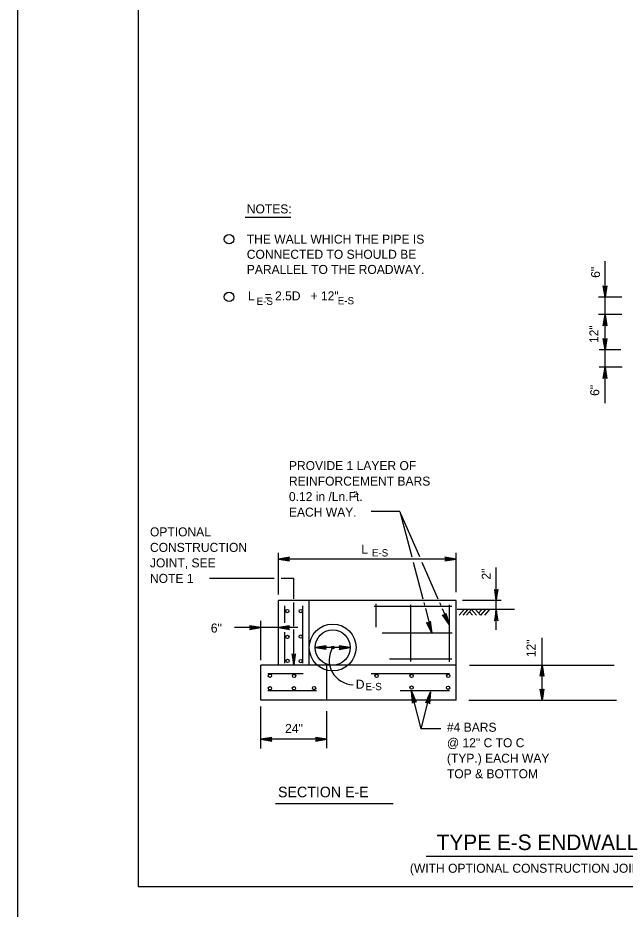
# Model space of a CAD drawing. Extents: x 638877 to 639960, y 297341 to 299123.
# Drawn here: x 638877.2 to 639079.3, y 297942.8 to 298239.6 of the extents above; entities that cross this region are included whole.
import ezdxf

# ---------------------------------------------------------------- set-up
doc = ezdxf.new("R2010")
doc.units = 0
for name, color, linetype in [('1', 7, 'Continuous'), ('2', 7, 'Continuous'), ('3', 7, 'Continuous'), ('PLT-BNDY', 7, 'Continuous')]:
    doc.layers.add(name, color=color, linetype=linetype)

msp = doc.modelspace()

# ---------------------------------------------------------------- linework, layer by layer
at = {"layer": '1'}
for p, q in [((638917.19, 298514.28), (638917.19, 297950.28)), ((639025.67, 298042.52), (639024.05, 298040.69)), ((639026.82, 298042.48), (639025.24, 298040.69)), ((639028.14, 298042.52), (639026.52, 298040.69)), ((639028.14, 298042.52), (639029.79, 298040.69)), ((639029.46, 298042.52), (639031.12, 298040.69)), ((639031.43, 298042.48), (639030.47, 298041.4)), ((639032.66, 298042.44), (639031.12, 298040.69)), ((639034.03, 298042.48), (639032.41, 298040.64)), ((639027.54, 298041.71), (639028.47, 298040.69)), ((639021.72, 298034.74), (638998.36, 298034.74)), ((638917.19, 297950.28), (639703.19, 297950.28))]:
    msp.add_line(p, q, dxfattribs=at)
for centre, radius in [((638947.46, 298165.86), 1.58), ((638947.46, 298146.66), 1.58), ((638966.85, 298042.05), 0.554), ((638971.31, 298042.05), 0.554), ((638981.95, 298029.91), 7.8), ((638966.88, 298033.46), 0.554), ((638971.31, 298033.57), 0.554), ((638981.95, 298029.91), 0.452), ((638966.93, 298025.47), 0.554), ((638971.31, 298025.37), 0.554), ((638961.06, 298020.51), 0.554), ((638969.08, 298020.44), 0.554), ((638996.57, 298020.47), 0.554), ((639008.21, 298020.46), 0.554), ((639020.38, 298020.44), 0.554), ((638961.04, 298016.35), 0.554), ((638969.04, 298016.33), 0.554), ((638975.75, 298016.38), 0.554), ((639008.19, 298016.59), 0.554), ((639020.35, 298016.49), 0.554)]:
    msp.add_circle(centre, radius, dxfattribs=at)
msp.add_arc((638988.96, 298025.7), 8.18, 149.0183, 268.6465, dxfattribs=at)
at = {"layer": '2'}
for p, q in [((638952.88, 298173.26), (638967.97, 298173.26)), ((639072.57, 298140.77), (639072.57, 298158.6)), ((639078.16, 298146.62), (639070.44, 298146.62)), ((639078.16, 298140.77), (639070.44, 298140.77)), ((639072.57, 298129.07), (639072.57, 298140.77)), ((639077.87, 298129.07), (639070.58, 298129.07)), ((639072.57, 298111.24), (639072.57, 298129.07)), ((639078.3, 298123.22), (639070.58, 298123.22)), ((639004.32, 298075.22), (638994.72, 298075.22)), ((639004.32, 298075.22), (639008.28, 298060.14)), ((639004.59, 298074.35), (639010.8, 298060.2)), ((638963.88, 298047.53), (638963.88, 298061.49)), ((639023.03, 298048.29), (639023.03, 298061.49)), ((639023.03, 298059.37), (638963.88, 298059.37)), ((639008.77, 298058.28), (639011.95, 298046.15)), ((639011.63, 298058.31), (639016.95, 298046.16)), ((639036.39, 298035.76), (639036.39, 298056.6)), ((638962.46, 298052.87), (638940.93, 298052.87)), ((638969.01, 298052.87), (638964.78, 298052.87)), ((638969.01, 298046.16), (638969.01, 298052.87)), ((638963.88, 298024.06), (638963.88, 298045.51)), ((639023.03, 298045.51), (638963.88, 298045.51)), ((638974.15, 298024.06), (638974.15, 298045.51)), ((639012.27, 298044.93), (639012.5, 298044.06)), ((639023.03, 298012.36), (639023.03, 298045.51)), ((639038.06, 298045.51), (639025.09, 298045.51)), ((638966.08, 298038.08), (638966.08, 298043.77)), ((638969.01, 298037.06), (638969.01, 298044.9)), ((638971.98, 298024.73), (638971.98, 298043.77)), ((639021.56, 298043.56), (638995.71, 298043.56)), ((638996.46, 298036.68), (638996.46, 298044.4)), ((639007.93, 298025.27), (639007.93, 298044.17)), ((639012.8, 298042.95), (639014.95, 298034.74)), ((639017.51, 298044.91), (639017.88, 298044.05)), ((639018.41, 298042.85), (639020.74, 298037.54)), ((639020.81, 298025.19), (639020.81, 298044.17)), ((639042.49, 298042.56), (639023.35, 298042.56)), ((638963.88, 298036.52), (638949.26, 298036.52)), ((638958.03, 298025.66), (638958.03, 298038.79)), ((638970.4, 298036.52), (638963.88, 298036.52)), ((638966.08, 298024.73), (638966.08, 298035.01)), ((638969.01, 298024.06), (638969.01, 298035.89)), ((639051.63, 298024.06), (639051.63, 298033.12)), ((638987.8, 298029.91), (638976.1, 298029.91)), ((638981.95, 298029.91), (638981.95, 298029.91)), ((639021.56, 298026.05), (639000.89, 298026.05)), ((638963.88, 298024.06), (638958.03, 298024.06)), ((638958.03, 298012.36), (638958.03, 298024.06)), ((638972.16, 298021.19), (638960.39, 298021.19)), ((638974.15, 298024.06), (638963.88, 298024.06)), ((639023.03, 298024.06), (638974.15, 298024.06)), ((638980, 298012.36), (638980, 298024.06)), ((639020.83, 298021.19), (638994.74, 298021.19)), ((639027.47, 298024.06), (639075.6, 298024.06)), ((639051.63, 298012.36), (639051.63, 298024.06)), ((638976.6, 298015.52), (638960.39, 298015.52)), ((639020.83, 298015.52), (639004.44, 298015.52)), ((639011.34, 298002.78), (639008.12, 298015.35)), ((639023.03, 298012.36), (638958.03, 298012.36)), ((639011.34, 298002.78), (639014.52, 298015.14)), ((639027.2, 298012.36), (639076.42, 298012.36)), ((638958.03, 297996.32), (638958.03, 298010.25)), ((638980, 297996.42), (638980, 298008.74)), ((639017.92, 298002.78), (639011.34, 298002.78)), ((638980, 297999.37), (638958.03, 297999.37))]:
    msp.add_line(p, q, dxfattribs=at)
for points in [[(639073.01, 298150.17), (639072.75, 298150.03), (639072.57, 298146.62), (639073.01, 298150.17), (639073.17, 298150.35), (639072.57, 298146.62), (639072.4, 298150.03), (639072.15, 298150.15), (639072.57, 298146.62), (639071.97, 298150.35), (639072.15, 298150.15)], [(639072.12, 298137.23), (639072.38, 298137.37), (639072.57, 298140.77), (639072.12, 298137.23), (639071.97, 298137.05), (639072.57, 298140.77), (639072.74, 298137.37), (639072.99, 298137.24), (639072.57, 298140.77), (639073.16, 298137.05), (639072.99, 298137.24)], [(639073.01, 298132.62), (639072.75, 298132.48), (639072.57, 298129.07), (639073.01, 298132.62), (639073.17, 298132.8), (639072.57, 298129.07), (639072.4, 298132.48), (639072.15, 298132.6), (639072.57, 298129.07), (639071.97, 298132.8), (639072.15, 298132.6)], [(639072.12, 298119.68), (639072.38, 298119.82), (639072.57, 298123.22), (639072.12, 298119.68), (639071.97, 298119.5), (639072.57, 298123.22), (639072.74, 298119.82), (639072.99, 298119.69), (639072.57, 298123.22), (639073.16, 298119.5), (639072.99, 298119.69)], [(638967.42, 298059.81), (638967.29, 298059.56), (638963.88, 298059.37), (638967.42, 298059.81), (638967.6, 298059.97), (638963.88, 298059.37), (638967.28, 298059.2), (638967.41, 298058.95), (638963.88, 298059.37), (638967.6, 298058.78), (638967.41, 298058.95)], [(639019.49, 298058.92), (639019.62, 298059.18), (639023.03, 298059.37), (639019.49, 298058.92), (639019.3, 298058.77), (639023.03, 298059.37), (639019.62, 298059.54), (639019.5, 298059.79), (639023.03, 298059.37), (639019.3, 298059.96), (639019.5, 298059.79)], [(639035.95, 298049.08), (639036.21, 298048.95), (639036.39, 298045.54), (639035.95, 298049.08), (639035.79, 298049.26), (639036.39, 298045.54), (639036.56, 298048.95), (639036.82, 298049.07), (639036.39, 298045.54), (639036.99, 298049.26), (639036.82, 298049.07)], [(639036.84, 298039), (639036.58, 298039.14), (639036.39, 298042.55), (639036.84, 298039), (639037, 298038.82), (639036.39, 298042.55), (639036.23, 298039.14), (639035.97, 298039.01), (639036.39, 298042.55), (639035.8, 298038.82), (639035.97, 298039.01)], [(639019.53, 298041.07), (639019.35, 298040.83), (639020.74, 298037.54), (639019.53, 298041.07), (639019.59, 298041.32), (639020.74, 298037.54), (639019.02, 298040.66), (639018.72, 298040.66), (639020.74, 298037.54), (639018.47, 298040.77), (639018.72, 298040.66)], [(638954.49, 298036.07), (638954.62, 298036.33), (638958.03, 298036.52), (638954.49, 298036.07), (638954.3, 298035.92), (638958.03, 298036.52), (638954.62, 298036.69), (638954.5, 298036.94), (638958.03, 298036.52), (638954.3, 298037.11), (638954.5, 298036.94)], [(638967.42, 298036.96), (638967.29, 298036.71), (638963.88, 298036.52), (638967.42, 298036.96), (638967.6, 298037.12), (638963.88, 298036.52), (638967.28, 298036.35), (638967.41, 298036.1), (638963.88, 298036.52), (638967.6, 298035.93), (638967.41, 298036.1)], [(639014.3, 298038.43), (639014.09, 298038.21), (639014.95, 298034.74), (639014.3, 298038.43), (639014.4, 298038.65), (639014.95, 298034.74), (639013.73, 298038.1), (639013.44, 298038.15), (639014.95, 298034.74), (639013.21, 298038.29), (639013.44, 298038.15)], [(638979.64, 298030.35), (638979.51, 298030.09), (638976.1, 298029.91), (638979.64, 298030.35), (638979.82, 298030.51), (638976.1, 298029.91), (638979.51, 298029.74), (638979.63, 298029.48), (638976.1, 298029.91), (638979.82, 298029.31), (638979.63, 298029.48)], [(638984.26, 298029.46), (638984.39, 298029.72), (638987.8, 298029.91), (638984.26, 298029.46), (638984.08, 298029.3), (638987.8, 298029.91), (638984.4, 298030.07), (638984.27, 298030.33), (638987.8, 298029.91), (638984.08, 298030.5), (638984.27, 298030.33)], [(638968.57, 298027.6), (638968.83, 298027.46), (638969.01, 298024.06), (638968.57, 298027.6), (638968.41, 298027.78), (638969.01, 298024.06), (638969.18, 298027.46), (638969.44, 298027.59), (638969.01, 298024.06), (638969.61, 298027.78), (638969.44, 298027.59)], [(639051.18, 298020.51), (639051.44, 298020.65), (639051.63, 298024.06), (639051.18, 298020.51), (639051.03, 298020.33), (639051.63, 298024.06), (639051.8, 298020.65), (639052.05, 298020.52), (639051.63, 298024.06), (639052.22, 298020.33), (639052.05, 298020.52)], [(639008.59, 298011.63), (639008.82, 298011.84), (639008.12, 298015.35), (639008.59, 298011.63), (639008.48, 298011.41), (639008.12, 298015.35), (639009.18, 298011.93), (639009.47, 298011.87), (639008.12, 298015.35), (639009.69, 298011.72), (639009.47, 298011.87)], [(639052.07, 298015.9), (639051.81, 298015.76), (639051.63, 298012.36), (639052.07, 298015.9), (639052.23, 298016.08), (639051.63, 298012.36), (639051.46, 298015.76), (639051.21, 298015.89), (639051.63, 298012.36), (639051.03, 298016.08), (639051.21, 298015.89)], [(639013.15, 298011.67), (639013.44, 298011.73), (639014.52, 298015.14), (639013.15, 298011.67), (639012.94, 298011.52), (639014.52, 298015.14), (639013.81, 298011.65), (639014.03, 298011.45), (639014.52, 298015.14), (639014.15, 298011.21), (639014.03, 298011.45)], [(638961.57, 297999.82), (638961.44, 297999.56), (638958.03, 297999.37), (638961.57, 297999.82), (638961.75, 297999.97), (638958.03, 297999.37), (638961.43, 297999.2), (638961.56, 297998.95), (638958.03, 297999.37), (638961.75, 297998.78), (638961.56, 297998.95)], [(638976.46, 297998.93), (638976.59, 297999.19), (638980, 297999.37), (638976.46, 297998.93), (638976.28, 297998.77), (638980, 297999.37), (638976.6, 297999.54), (638976.47, 297999.79), (638980, 297999.37), (638976.28, 297999.97), (638976.47, 297999.79)]]:
    msp.add_lwpolyline(points, dxfattribs=at)
msp.add_circle((638981.95, 298029.91), 5.85, dxfattribs=at)
at = {"layer": '3'}
for p, q in [((638962.96, 297977.97), (639002.12, 297977.97)), ((639013.06, 297960.43), (639100.36, 297960.43))]:
    msp.add_line(p, q, dxfattribs=at)
at = {"layer": 'PLT-BNDY'}
msp.add_lwpolyline([(638877.19, 298529.28), (639718.19, 298529.28), (639718.19, 297935.28), (638877.19, 297935.28)], close=True, dxfattribs=at)

# ---------------------------------------------------------------- texts
at = {"layer": '1'}
for s, height, p in [('NOTES:', 3, (638953.37, 298174.46)), ('THE WALL WHICH THE PIPE IS', 2.9999, (638953.37, 298164.38)), ('CONNECTED TO SHOULD BE', 2.9999, (638953.37, 298159.34)), ('PARALLEL TO THE ROADWAY.', 2.9999, (638953.37, 298154.3)), ('L   = 2.5D   + 12"', 2.9999, (638953.74, 298145.5)), ('E-S', 2.43, (638956.65, 298144)), ('E-S', 2.43, (638983.64, 298144.19)), ('2', 1.8, (638988.84, 298080.13)), ('E-S', 2.43, (638995.01, 298060.22)), ('D', 3, (638989.64, 298016.18)), ('E-S', 2.43, (638992.86, 298015.7))]:
    msp.add_text(s, height=height, dxfattribs=at).set_placement(p)
at = {"layer": '2'}
msp.add_text('L', height=3, dxfattribs=at).set_placement((638991.49, 298061.21))
at = {"layer": '3'}
for s, p in [('6"', (639070.91, 298153.01)), ('12"', (639070.38, 298131.3)), ('6"', (639070.64, 298113.7)), ('2"', (639034.52, 298052.53)), ('12"', (639049.45, 298026.7))]:
    msp.add_text(s, height=3, rotation=90, dxfattribs=at).set_placement(p)
for s, height, p in [('PROVIDE 1 LAYER OF', 2.9999, (638967.39, 298088.98)), ('REINFORCEMENT BARS', 2.9999, (638967.39, 298083.82)), ('0.12 in /Ln.Ft. ', 2.9999, (638967.39, 298078.66)), ('EACH WAY.', 3, (638967.39, 298073.5)), ('OPTIONAL', 3, (638921.15, 298066.91)), ('CONSTRUCTION', 2.9999, (638921.15, 298061.75)), ('JOINT, SEE', 3, (638921.15, 298056.59)), ('NOTE 1', 3, (638921.15, 298051.43)), ('6"', 3, (638941.4, 298034.89)), ('24"', 3, (638966.13, 298001.46)), ('#4 BARS', 3, (639019.96, 298001.86)), ('@ 12" C TO C', 2.9999, (639019.96, 297996.7)), ('(TYP.) EACH WAY', 2.9999, (639019.96, 297991.54)), ('TOP & BOTTOM', 2.9999, (639019.96, 297986.38)), ('SECTION E-E', 3.5299, (638963.76, 297980.04)), ('TYPE E-S ENDWALL', 5.1858, (639016.54, 297962.46)), ('(WITH OPTIONAL CONSTRUCTION JOINT)', 2.9999, (639007.65, 297954.91))]:
    msp.add_text(s, height=height, dxfattribs=at).set_placement(p)

doc.saveas('drawing.dxf')
